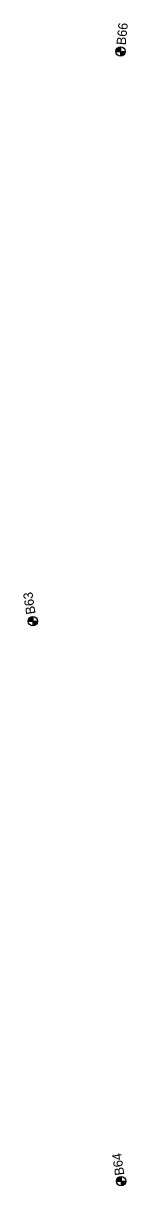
# Model space of a CAD drawing. Extents: x 335726 to 369746, y 119154 to 200788.
# Drawn here: x 359339 to 359451, y 164656 to 165893 of the extents above; entities that cross this region are included whole.
import ezdxf

# ---------------------------------------------------------------- set-up
doc = ezdxf.new("R2010")
doc.units = 0
for name, color, linetype in [('E_SOIL_BORE1 [KAPUR_CADDS_LEVELS]', 7, 'Continuous'), ('E_SOIL_BORE2 [KAPUR_CADDS_LEVELS]', 7, 'Continuous'), ('P_MARK', 7, 'Continuous')]:
    doc.layers.add(name, color=color, linetype=linetype)

msp = doc.modelspace()

# ---------------------------------------------------------------- linework, layer by layer
at = {"layer": 'P_MARK'}
for p, q in [((359437.8, 165863.3), (359447.8, 165863.3)), ((359442.8, 165868.3), (359442.8, 165858.3)), ((359344.2, 165256.8), (359354.2, 165256.8)), ((359349.2, 165261.8), (359349.2, 165251.8)), ((359438.4, 164660.9), (359448.4, 164660.9)), ((359443.4, 164665.9), (359443.4, 164655.9))]:
    msp.add_line(p, q, dxfattribs=at)
for centre in [(359442.8, 165863.3), (359349.2, 165256.8), (359443.4, 164660.9)]:
    msp.add_circle(centre, 5, dxfattribs=at)
for centre, radius, start, end in [((359442.8, 165863.3), 4.5, 89.9869, 179.9869), ((359442.8, 165863.3), 4, 89.9869, 179.9869), ((359442.8, 165863.3), 3.5, 89.9869, 179.9869), ((359442.8, 165863.3), 3, 89.9869, 179.9869), ((359442.8, 165863.3), 2.5, 89.9869, 179.9869), ((359442.8, 165863.3), 2, 89.9869, 179.9869), ((359442.8, 165863.3), 1.5, 89.9869, 179.9869), ((359442.8, 165863.3), 1, 89.9869, 179.9869), ((359442.8, 165863.3), 0.5, 89.9869, 179.9869), ((359442.8, 165863.3), 4.5, 269.9869, 359.9869), ((359442.8, 165863.3), 4, 269.9869, 359.9869), ((359442.8, 165863.3), 3.5, 269.9869, 359.9869), ((359442.8, 165863.3), 3, 269.9869, 359.9869), ((359442.8, 165863.3), 2.5, 269.9869, 359.9869), ((359442.8, 165863.3), 2, 269.9869, 359.9869), ((359442.8, 165863.3), 1.5, 269.9869, 359.9869), ((359442.8, 165863.3), 1, 269.9869, 359.9869), ((359442.8, 165863.3), 0.5, 269.9869, 359.9869), ((359349.2, 165256.8), 4.5, 89.9869, 179.9869), ((359349.2, 165256.8), 4, 89.9869, 179.9869), ((359349.2, 165256.8), 3.5, 89.9869, 179.9869), ((359349.2, 165256.8), 3, 89.9869, 179.9869), ((359349.2, 165256.8), 2.5, 89.9869, 179.9869), ((359349.2, 165256.8), 2, 89.9869, 179.9869), ((359349.2, 165256.8), 1.5, 89.9869, 179.9869), ((359349.2, 165256.8), 1, 89.9869, 179.9869), ((359349.2, 165256.8), 0.5, 89.9869, 179.9869), ((359349.2, 165256.8), 4.5, 269.9869, 359.9869), ((359349.2, 165256.8), 4, 269.9869, 359.9869), ((359349.2, 165256.8), 3.5, 269.9869, 359.9869), ((359349.2, 165256.8), 3, 269.9869, 359.9869), ((359349.2, 165256.8), 2.5, 269.9869, 359.9869), ((359349.2, 165256.8), 2, 269.9869, 359.9869), ((359349.2, 165256.8), 1.5, 269.9869, 359.9869), ((359349.2, 165256.8), 1, 269.9869, 359.9869), ((359349.2, 165256.8), 0.5, 269.9869, 359.9869), ((359443.4, 164660.9), 4.5, 89.9869, 179.9869), ((359443.4, 164660.9), 4, 89.9869, 179.9869), ((359443.4, 164660.9), 3.5, 89.9869, 179.9869), ((359443.4, 164660.9), 3, 89.9869, 179.9869), ((359443.4, 164660.9), 2.5, 89.9869, 179.9869), ((359443.4, 164660.9), 2, 89.9869, 179.9869), ((359443.4, 164660.9), 1.5, 89.9869, 179.9869), ((359443.4, 164660.9), 1, 89.9869, 179.9869), ((359443.4, 164660.9), 0.5, 89.9869, 179.9869), ((359443.4, 164660.9), 4.5, 269.9869, 359.9869), ((359443.4, 164660.9), 4, 269.9869, 359.9869), ((359443.4, 164660.9), 3.5, 269.9869, 359.9869), ((359443.4, 164660.9), 3, 269.9869, 359.9869), ((359443.4, 164660.9), 2.5, 269.9869, 359.9869), ((359443.4, 164660.9), 2, 269.9869, 359.9869), ((359443.4, 164660.9), 1.5, 269.9869, 359.9869), ((359443.4, 164660.9), 1, 269.9869, 359.9869), ((359443.4, 164660.9), 0.5, 269.9869, 359.9869)]:
    msp.add_arc(centre, radius, start, end, dxfattribs=at)

# ---------------------------------------------------------------- texts
at = {"layer": 'E_SOIL_BORE1 [KAPUR_CADDS_LEVELS]'}
for s, p in [('B63', (359352.1, 165264.9)), ('B64', (359447, 164667.6))]:
    msp.add_text(s, height=10, rotation=98.5151, dxfattribs=at).set_placement(p)
at = {"layer": 'E_SOIL_BORE2 [KAPUR_CADDS_LEVELS]'}
msp.add_text('B66', height=10, rotation=84.1728, dxfattribs=at).set_placement((359448.3, 165869.7))

doc.saveas('drawing.dxf')
